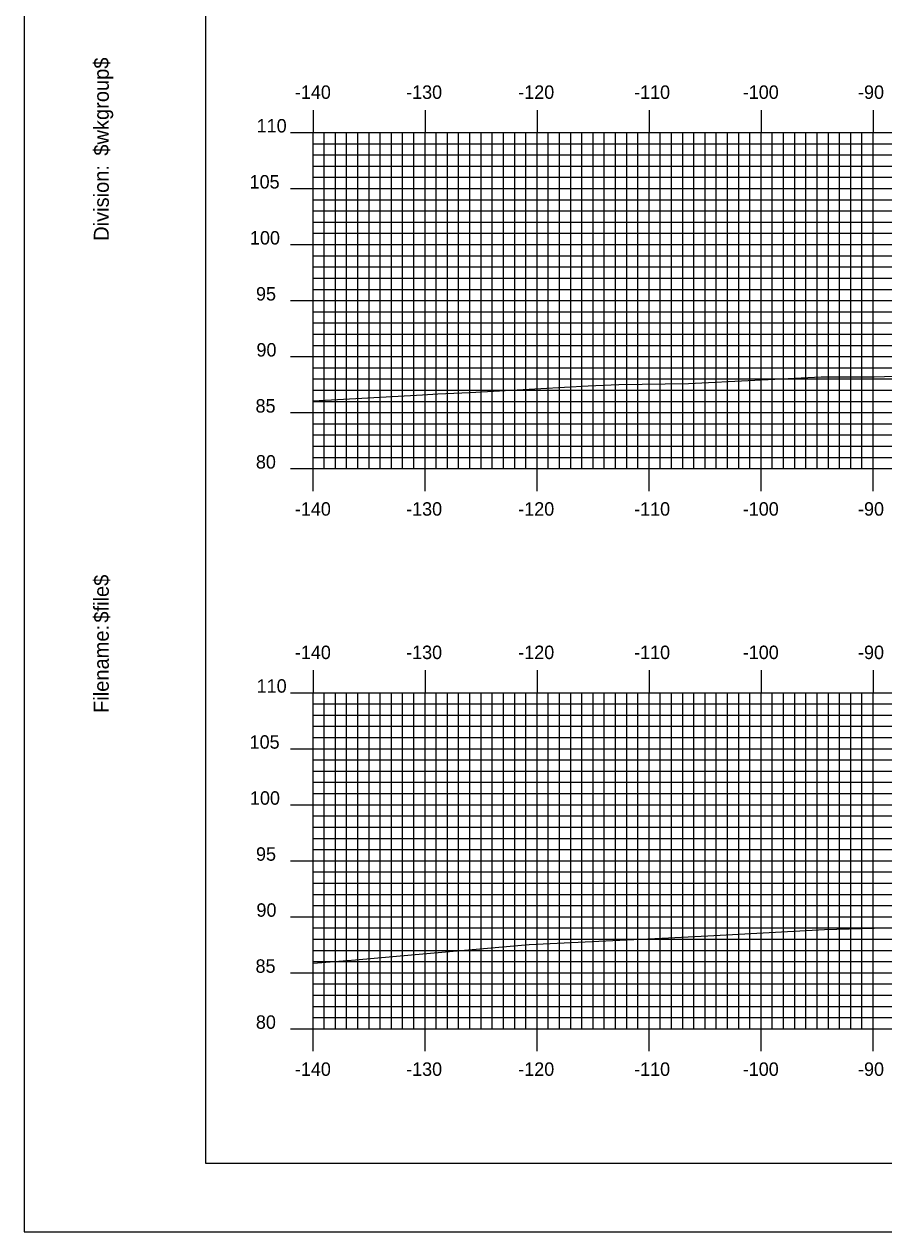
# Model space of a CAD drawing. Extents: x 1272 to 1616, y -1658 to -1438.
# Drawn here: x 1272.4 to 1349.1, y -1657.7 to -1549.9 of the extents above; entities that cross this region are included whole.
import ezdxf

# ---------------------------------------------------------------- set-up
doc = ezdxf.new("R2010")
doc.units = 0
for name, color, linetype in [('BORDER', 7, 'Continuous'), ('H_V ANNOTATION', 7, 'Continuous'), ('MAJOR', 7, 'Continuous'), ('MINOR', 7, 'Continuous'), ('PLOT BOUNDARY', 7, 'Continuous'), ('S_Roadway_Centerline', 7, 'Continuous')]:
    doc.layers.add(name, color=color, linetype=linetype)

msp = doc.modelspace()

# ---------------------------------------------------------------- linework, layer by layer
at = {"layer": 'BORDER'}
msp.add_lwpolyline([(1288.56, -1651.6), (1608.56, -1651.6), (1608.56, -1441.6), (1288.56, -1441.6)], close=True, dxfattribs=at)
at = {"layer": 'MAJOR'}
for p, q in [((1298.16, -1557.6), (1298.16, -1559.6)), ((1308.16, -1557.6), (1308.16, -1559.6)), ((1318.16, -1557.6), (1318.16, -1559.6)), ((1328.16, -1557.6), (1328.16, -1559.6)), ((1338.16, -1557.6), (1338.16, -1559.6)), ((1348.16, -1557.6), (1348.16, -1559.6)), ((1296.16, -1559.6), (1298.16, -1559.6)), ((1298.16, -1559.6), (1578.16, -1559.6)), ((1298.16, -1589.6), (1298.16, -1559.6)), ((1298.16, -1589.6), (1298.16, -1559.6)), ((1298.16, -1559.6), (1578.16, -1559.6)), ((1308.16, -1589.6), (1308.16, -1559.6)), ((1318.16, -1589.6), (1318.16, -1559.6)), ((1328.16, -1589.6), (1328.16, -1559.6)), ((1338.16, -1589.6), (1338.16, -1559.6)), ((1348.16, -1589.6), (1348.16, -1559.6)), ((1296.16, -1564.6), (1298.16, -1564.6)), ((1298.16, -1564.6), (1578.16, -1564.6)), ((1296.16, -1569.6), (1298.16, -1569.6)), ((1298.16, -1569.6), (1578.16, -1569.6)), ((1296.16, -1574.6), (1298.16, -1574.6)), ((1298.16, -1574.6), (1578.16, -1574.6)), ((1296.16, -1579.6), (1298.16, -1579.6)), ((1298.16, -1579.6), (1578.16, -1579.6)), ((1296.16, -1584.6), (1298.16, -1584.6)), ((1298.16, -1584.6), (1578.16, -1584.6)), ((1296.16, -1589.6), (1298.16, -1589.6)), ((1298.16, -1589.6), (1578.16, -1589.6)), ((1298.16, -1589.6), (1578.16, -1589.6)), ((1298.16, -1591.61), (1298.16, -1589.6)), ((1308.16, -1591.61), (1308.16, -1589.6)), ((1318.16, -1591.61), (1318.16, -1589.6)), ((1328.16, -1591.61), (1328.16, -1589.6)), ((1338.16, -1591.61), (1338.16, -1589.6)), ((1348.16, -1591.61), (1348.16, -1589.6)), ((1298.16, -1607.6), (1298.16, -1609.6)), ((1308.16, -1607.6), (1308.16, -1609.6)), ((1318.16, -1607.6), (1318.16, -1609.6)), ((1328.16, -1607.6), (1328.16, -1609.6)), ((1338.16, -1607.6), (1338.16, -1609.6)), ((1348.16, -1607.6), (1348.16, -1609.6)), ((1296.16, -1609.6), (1298.16, -1609.6)), ((1298.16, -1609.6), (1578.16, -1609.6)), ((1298.16, -1639.6), (1298.16, -1609.6)), ((1298.16, -1639.6), (1298.16, -1609.6)), ((1298.16, -1609.6), (1578.16, -1609.6)), ((1308.16, -1639.6), (1308.16, -1609.6)), ((1318.16, -1639.6), (1318.16, -1609.6)), ((1328.16, -1639.6), (1328.16, -1609.6)), ((1338.16, -1639.6), (1338.16, -1609.6)), ((1348.16, -1639.6), (1348.16, -1609.6)), ((1296.16, -1614.6), (1298.16, -1614.6)), ((1298.16, -1614.6), (1578.16, -1614.6)), ((1296.16, -1619.6), (1298.16, -1619.6)), ((1298.16, -1619.6), (1578.16, -1619.6)), ((1296.16, -1624.6), (1298.16, -1624.6)), ((1298.16, -1624.6), (1578.16, -1624.6)), ((1296.16, -1629.6), (1298.16, -1629.6)), ((1298.16, -1629.6), (1578.16, -1629.6)), ((1296.16, -1634.6), (1298.16, -1634.6)), ((1298.16, -1634.6), (1578.16, -1634.6)), ((1296.16, -1639.6), (1298.16, -1639.6)), ((1298.16, -1639.6), (1578.16, -1639.6)), ((1298.16, -1639.6), (1578.16, -1639.6)), ((1298.16, -1641.61), (1298.16, -1639.6)), ((1308.16, -1641.61), (1308.16, -1639.6)), ((1318.16, -1641.61), (1318.16, -1639.6)), ((1328.16, -1641.61), (1328.16, -1639.6)), ((1338.16, -1641.61), (1338.16, -1639.6)), ((1348.16, -1641.61), (1348.16, -1639.6))]:
    msp.add_line(p, q, dxfattribs=at)
at = {"layer": 'MINOR'}
for p, q in [((1299.16, -1589.6), (1299.16, -1559.6)), ((1300.16, -1589.6), (1300.16, -1559.6)), ((1301.16, -1589.6), (1301.16, -1559.6)), ((1302.16, -1589.6), (1302.16, -1559.6)), ((1303.16, -1589.6), (1303.16, -1559.6)), ((1304.16, -1589.6), (1304.16, -1559.6)), ((1305.16, -1589.6), (1305.16, -1559.6)), ((1306.16, -1589.6), (1306.16, -1559.6)), ((1307.16, -1589.6), (1307.16, -1559.6)), ((1309.16, -1589.6), (1309.16, -1559.6)), ((1310.16, -1589.6), (1310.16, -1559.6)), ((1311.16, -1589.6), (1311.16, -1559.6)), ((1312.16, -1589.6), (1312.16, -1559.6)), ((1313.16, -1589.6), (1313.16, -1559.6)), ((1314.16, -1589.6), (1314.16, -1559.6)), ((1315.16, -1589.6), (1315.16, -1559.6)), ((1316.16, -1589.6), (1316.16, -1559.6)), ((1317.16, -1589.6), (1317.16, -1559.6)), ((1319.16, -1589.6), (1319.16, -1559.6)), ((1320.16, -1589.6), (1320.16, -1559.6)), ((1321.16, -1589.6), (1321.16, -1559.6)), ((1322.16, -1589.6), (1322.16, -1559.6)), ((1323.16, -1589.6), (1323.16, -1559.6)), ((1324.16, -1589.6), (1324.16, -1559.6)), ((1325.16, -1589.6), (1325.16, -1559.6)), ((1326.16, -1589.6), (1326.16, -1559.6)), ((1327.16, -1589.6), (1327.16, -1559.6)), ((1329.16, -1589.6), (1329.16, -1559.6)), ((1330.16, -1589.6), (1330.16, -1559.6)), ((1331.16, -1589.6), (1331.16, -1559.6)), ((1332.16, -1589.6), (1332.16, -1559.6)), ((1333.16, -1589.6), (1333.16, -1559.6)), ((1334.16, -1589.6), (1334.16, -1559.6)), ((1335.16, -1589.6), (1335.16, -1559.6)), ((1336.16, -1589.6), (1336.16, -1559.6)), ((1337.16, -1589.6), (1337.16, -1559.6)), ((1339.16, -1589.6), (1339.16, -1559.6)), ((1340.16, -1589.6), (1340.16, -1559.6)), ((1341.16, -1589.6), (1341.16, -1559.6)), ((1342.16, -1589.6), (1342.16, -1559.6)), ((1343.16, -1589.6), (1343.16, -1559.6)), ((1344.16, -1589.6), (1344.16, -1559.6)), ((1345.16, -1589.6), (1345.16, -1559.6)), ((1346.16, -1589.6), (1346.16, -1559.6)), ((1347.16, -1589.6), (1347.16, -1559.6)), ((1298.16, -1560.6), (1578.16, -1560.6)), ((1298.16, -1560.6), (1300.16, -1560.6)), ((1298.16, -1561.6), (1578.16, -1561.6)), ((1298.16, -1561.6), (1300.16, -1561.6)), ((1298.16, -1562.6), (1578.16, -1562.6)), ((1298.16, -1562.6), (1300.16, -1562.6)), ((1298.16, -1563.6), (1578.16, -1563.6)), ((1298.16, -1563.6), (1300.16, -1563.6)), ((1298.16, -1565.6), (1578.16, -1565.6)), ((1298.16, -1565.6), (1300.16, -1565.6)), ((1298.16, -1566.6), (1578.16, -1566.6)), ((1298.16, -1566.6), (1300.16, -1566.6)), ((1298.16, -1567.6), (1578.16, -1567.6)), ((1298.16, -1567.6), (1300.16, -1567.6)), ((1298.16, -1568.6), (1578.16, -1568.6)), ((1298.16, -1568.6), (1300.16, -1568.6)), ((1298.16, -1570.6), (1578.16, -1570.6)), ((1298.16, -1570.6), (1300.16, -1570.6)), ((1298.16, -1571.6), (1578.16, -1571.6)), ((1298.16, -1571.6), (1300.16, -1571.6)), ((1298.16, -1572.6), (1578.16, -1572.6)), ((1298.16, -1572.6), (1300.16, -1572.6)), ((1298.16, -1573.6), (1578.16, -1573.6)), ((1298.16, -1573.6), (1300.16, -1573.6)), ((1298.16, -1575.6), (1578.16, -1575.6)), ((1298.16, -1575.6), (1300.16, -1575.6)), ((1298.16, -1576.6), (1578.16, -1576.6)), ((1298.16, -1576.6), (1300.16, -1576.6)), ((1298.16, -1577.6), (1578.16, -1577.6)), ((1298.16, -1577.6), (1300.16, -1577.6)), ((1298.16, -1578.6), (1578.16, -1578.6)), ((1298.16, -1578.6), (1300.16, -1578.6)), ((1298.16, -1580.6), (1578.16, -1580.6)), ((1298.16, -1580.6), (1300.16, -1580.6)), ((1298.16, -1581.6), (1578.16, -1581.6)), ((1298.16, -1581.6), (1300.16, -1581.6)), ((1298.16, -1582.6), (1578.16, -1582.6)), ((1298.16, -1582.6), (1300.16, -1582.6)), ((1298.16, -1583.6), (1578.16, -1583.6)), ((1298.16, -1583.6), (1300.16, -1583.6)), ((1298.16, -1585.6), (1578.16, -1585.6)), ((1298.16, -1585.6), (1300.16, -1585.6)), ((1298.16, -1586.6), (1578.16, -1586.6)), ((1298.16, -1586.6), (1300.16, -1586.6)), ((1298.16, -1587.6), (1578.16, -1587.6)), ((1298.16, -1587.6), (1300.16, -1587.6)), ((1298.16, -1588.6), (1578.16, -1588.6)), ((1298.16, -1588.6), (1300.16, -1588.6)), ((1299.16, -1639.6), (1299.16, -1609.6)), ((1300.16, -1639.6), (1300.16, -1609.6)), ((1301.16, -1639.6), (1301.16, -1609.6)), ((1302.16, -1639.6), (1302.16, -1609.6)), ((1303.16, -1639.6), (1303.16, -1609.6)), ((1304.16, -1639.6), (1304.16, -1609.6)), ((1305.16, -1639.6), (1305.16, -1609.6)), ((1306.16, -1639.6), (1306.16, -1609.6)), ((1307.16, -1639.6), (1307.16, -1609.6)), ((1309.16, -1639.6), (1309.16, -1609.6)), ((1310.16, -1639.6), (1310.16, -1609.6)), ((1311.16, -1639.6), (1311.16, -1609.6)), ((1312.16, -1639.6), (1312.16, -1609.6)), ((1313.16, -1639.6), (1313.16, -1609.6)), ((1314.16, -1639.6), (1314.16, -1609.6)), ((1315.16, -1639.6), (1315.16, -1609.6)), ((1316.16, -1639.6), (1316.16, -1609.6)), ((1317.16, -1639.6), (1317.16, -1609.6)), ((1319.16, -1639.6), (1319.16, -1609.6)), ((1320.16, -1639.6), (1320.16, -1609.6)), ((1321.16, -1639.6), (1321.16, -1609.6)), ((1322.16, -1639.6), (1322.16, -1609.6)), ((1323.16, -1639.6), (1323.16, -1609.6)), ((1324.16, -1639.6), (1324.16, -1609.6)), ((1325.16, -1639.6), (1325.16, -1609.6)), ((1326.16, -1639.6), (1326.16, -1609.6)), ((1327.16, -1639.6), (1327.16, -1609.6)), ((1329.16, -1639.6), (1329.16, -1609.6)), ((1330.16, -1639.6), (1330.16, -1609.6)), ((1331.16, -1639.6), (1331.16, -1609.6)), ((1332.16, -1639.6), (1332.16, -1609.6)), ((1333.16, -1639.6), (1333.16, -1609.6)), ((1334.16, -1639.6), (1334.16, -1609.6)), ((1335.16, -1639.6), (1335.16, -1609.6)), ((1336.16, -1639.6), (1336.16, -1609.6)), ((1337.16, -1639.6), (1337.16, -1609.6)), ((1339.16, -1639.6), (1339.16, -1609.6)), ((1340.16, -1639.6), (1340.16, -1609.6)), ((1341.16, -1639.6), (1341.16, -1609.6)), ((1342.16, -1639.6), (1342.16, -1609.6)), ((1343.16, -1639.6), (1343.16, -1609.6)), ((1344.16, -1639.6), (1344.16, -1609.6)), ((1345.16, -1639.6), (1345.16, -1609.6)), ((1346.16, -1639.6), (1346.16, -1609.6)), ((1347.16, -1639.6), (1347.16, -1609.6)), ((1298.16, -1610.6), (1578.16, -1610.6)), ((1298.16, -1610.6), (1300.16, -1610.6)), ((1298.16, -1611.6), (1578.16, -1611.6)), ((1298.16, -1611.6), (1300.16, -1611.6)), ((1298.16, -1612.6), (1578.16, -1612.6)), ((1298.16, -1612.6), (1300.16, -1612.6)), ((1298.16, -1613.6), (1578.16, -1613.6)), ((1298.16, -1613.6), (1300.16, -1613.6)), ((1298.16, -1615.6), (1578.16, -1615.6)), ((1298.16, -1615.6), (1300.16, -1615.6)), ((1298.16, -1616.6), (1578.16, -1616.6)), ((1298.16, -1616.6), (1300.16, -1616.6)), ((1298.16, -1617.6), (1578.16, -1617.6)), ((1298.16, -1617.6), (1300.16, -1617.6)), ((1298.16, -1618.6), (1578.16, -1618.6)), ((1298.16, -1618.6), (1300.16, -1618.6)), ((1298.16, -1620.6), (1578.16, -1620.6)), ((1298.16, -1620.6), (1300.16, -1620.6)), ((1298.16, -1621.6), (1578.16, -1621.6)), ((1298.16, -1621.6), (1300.16, -1621.6)), ((1298.16, -1622.6), (1578.16, -1622.6)), ((1298.16, -1622.6), (1300.16, -1622.6)), ((1298.16, -1623.6), (1578.16, -1623.6)), ((1298.16, -1623.6), (1300.16, -1623.6)), ((1298.16, -1625.6), (1578.16, -1625.6)), ((1298.16, -1625.6), (1300.16, -1625.6)), ((1298.16, -1626.6), (1578.16, -1626.6)), ((1298.16, -1626.6), (1300.16, -1626.6)), ((1298.16, -1627.6), (1578.16, -1627.6)), ((1298.16, -1627.6), (1300.16, -1627.6)), ((1298.16, -1628.6), (1578.16, -1628.6)), ((1298.16, -1628.6), (1300.16, -1628.6)), ((1298.16, -1630.6), (1578.16, -1630.6)), ((1298.16, -1630.6), (1300.16, -1630.6)), ((1298.16, -1631.6), (1578.16, -1631.6)), ((1298.16, -1631.6), (1300.16, -1631.6)), ((1298.16, -1632.6), (1578.16, -1632.6)), ((1298.16, -1632.6), (1300.16, -1632.6)), ((1298.16, -1633.6), (1578.16, -1633.6)), ((1298.16, -1633.6), (1300.16, -1633.6)), ((1298.16, -1635.6), (1578.16, -1635.6)), ((1298.16, -1635.6), (1300.16, -1635.6)), ((1298.16, -1636.6), (1578.16, -1636.6)), ((1298.16, -1636.6), (1300.16, -1636.6)), ((1298.16, -1637.6), (1578.16, -1637.6)), ((1298.16, -1637.6), (1300.16, -1637.6)), ((1298.16, -1638.6), (1578.16, -1638.6)), ((1298.16, -1638.6), (1300.16, -1638.6))]:
    msp.add_line(p, q, dxfattribs=at)
at = {"layer": 'PLOT BOUNDARY'}
msp.add_lwpolyline([(1272.37, -1657.72), (1612.37, -1657.72), (1612.37, -1437.72), (1272.37, -1437.72)], close=True, dxfattribs=at)
at = {"layer": 'S_Roadway_Centerline'}
for points in [[(1298.16, -1583.56), (1307.94, -1583.03), (1309.29, -1582.94), (1312.15, -1582.8), (1322.73, -1582.22), (1325.46, -1582.08), (1331.67, -1581.99), (1343.52, -1581.4), (1348.24, -1581.42), (1361.34, -1581), (1362.22, -1580.99), (1364.56, -1580.94), (1377.65, -1580.55), (1388.11, -1580.26), (1395.72, -1580.04), (1400.92, -1579.96), (1412.64, -1579.29), (1413.89, -1579.26), (1417.66, -1579.21), (1430.51, -1579.17)], [(1298.16, -1633.74), (1300.46, -1633.57), (1301.96, -1633.44), (1306.95, -1633.01), (1317.46, -1632.09), (1329.31, -1631.5), (1333.41, -1631.31), (1343.82, -1630.75), (1350.46, -1630.57), (1358.78, -1630.24), (1367.55, -1629.97), (1381.18, -1629.6), (1384.99, -1629.58), (1387.41, -1629.56), (1400.91, -1629.81), (1401.27, -1629.81), (1403.07, -1629.78), (1418.67, -1629.53), (1427.2, -1629.3)]]:
    msp.add_lwpolyline(points, dxfattribs=at)

# ---------------------------------------------------------------- texts
at = {"layer": 'BORDER'}
for s, p in [('$wkgroup$', (1279.93, -1561.67)), ('Division:', (1279.93, -1569.27)), ('$file$', (1279.93, -1603.35)), ('Filename:', (1279.93, -1611.41))]:
    msp.add_text(s, height=1.339, rotation=90, dxfattribs=at).set_placement(p)
at = {"layer": 'H_V ANNOTATION'}
for s, p in [('-140', (1296.54, -1556.6)), ('-130', (1306.47, -1556.6)), ('-120', (1316.48, -1556.6)), ('-110', (1326.82, -1556.6)), ('-100', (1336.52, -1556.6)), ('-90', (1346.81, -1556.6)), ('110', (1293.13, -1559.6)), ('105', (1292.5, -1564.6)), ('100', (1292.53, -1569.6)), ('95', (1293.07, -1574.6)), ('90', (1293.11, -1579.6)), ('85', (1293.03, -1584.6)), ('80', (1293.06, -1589.6)), ('-140', (1296.54, -1593.8)), ('-130', (1306.47, -1593.8)), ('-120', (1316.48, -1593.8)), ('-110', (1326.82, -1593.8)), ('-100', (1336.52, -1593.8)), ('-90', (1346.81, -1593.8)), ('-140', (1296.54, -1606.6)), ('-130', (1306.47, -1606.6)), ('-120', (1316.48, -1606.6)), ('-110', (1326.82, -1606.6)), ('-100', (1336.52, -1606.6)), ('-90', (1346.81, -1606.6)), ('110', (1293.13, -1609.6)), ('105', (1292.5, -1614.6)), ('100', (1292.53, -1619.6)), ('95', (1293.07, -1624.6)), ('90', (1293.11, -1629.6)), ('85', (1293.03, -1634.6)), ('80', (1293.06, -1639.6)), ('-140', (1296.54, -1643.8)), ('-130', (1306.47, -1643.8)), ('-120', (1316.48, -1643.8)), ('-110', (1326.82, -1643.8)), ('-100', (1336.52, -1643.8)), ('-90', (1346.81, -1643.8))]:
    msp.add_text(s, height=1.2, dxfattribs=at).set_placement(p)
at = {"layer": 'MAJOR'}
for p in [(1298.15, -1589.6), (1298.15, -1639.6)]:
    msp.add_text('-', height=0.012, dxfattribs=at).set_placement(p)

doc.saveas('drawing.dxf')
